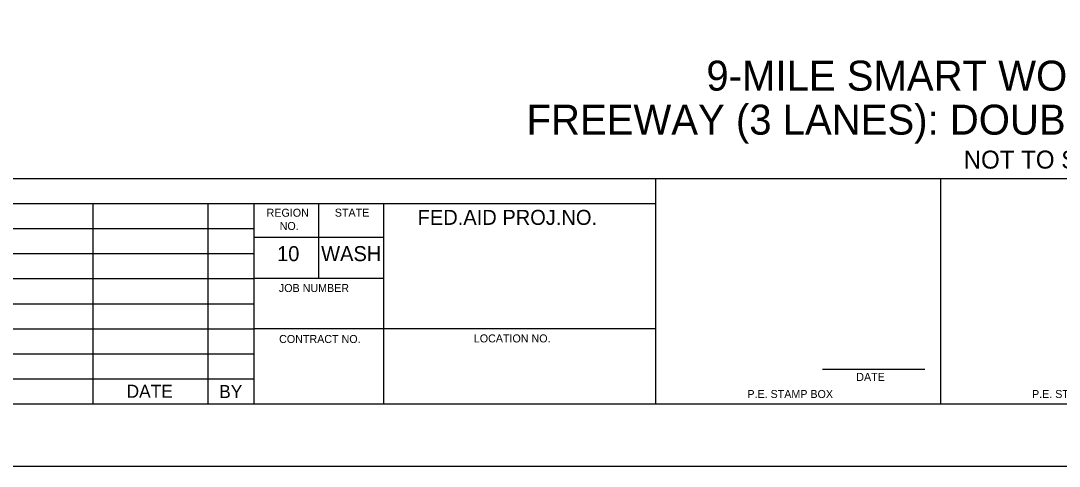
# Model space of a CAD drawing. Extents: x 99999.1 to 100055.7, y 99995 to 100017.5.
# Drawn here: x 100024.28 to 100029.47, y 99999.69 to 100001.92 of the extents above; entities that cross this region are included whole.
import ezdxf

# ---------------------------------------------------------------- set-up
doc = ezdxf.new("R2010")
doc.units = 0
for name, color, linetype in [('SH_DE_DetailHeading1Text', 7, 'Continuous'), ('SH_DE_DetailHeading3Text', 7, 'Continuous'), ('SH_GI_PlotLimits', 7, 'Continuous'), ('SH_GI_SheetBorder', 7, 'Continuous'), ('SH_GI_SheetTextInCells', 7, 'Continuous')]:
    doc.layers.add(name, color=color, linetype=linetype)

msp = doc.modelspace()

# ---------------------------------------------------------------- linework, layer by layer
at = {"layer": 'SH_GI_PlotLimits'}
msp.add_lwpolyline([(100019.0625, 99999.6875), (100036.0625, 99999.6875), (100036.0625, 100010.6875), (100019.0625, 100010.6875)], close=True, dxfattribs=at)
at = {"layer": 'SH_GI_SheetBorder'}
for p, q in [((100020, 100001.1259), (100035.75, 100001.1259)), ((100027.4566, 100000), (100027.4566, 100001.1259)), ((100028.8828, 100000), (100028.8828, 100001.1259)), ((100020, 100001.0008), (100027.4566, 100001.0008)), ((100024.641, 100001.0008), (100024.641, 100000)), ((100025.2164, 100001.0008), (100025.2164, 100000)), ((100025.4451, 100001.0008), (100025.4451, 100000)), ((100025.7719, 100000.6255), (100025.7719, 100001.0008)), ((100026.0956, 100000), (100026.0956, 100001.0008)), ((100022.1821, 100000.8757), (100025.4466, 100000.8757)), ((100026.0958, 100000.831), (100025.4466, 100000.831)), ((100022.1821, 100000.7506), (100025.4466, 100000.7506)), ((100020, 100000.6255), (100025.4466, 100000.6255)), ((100026.0958, 100000.6255), (100025.4466, 100000.6255)), ((100020, 100000.5004), (100025.4466, 100000.5004)), ((100020, 100000.3753), (100025.4466, 100000.3753)), ((100027.4566, 100000.3753), (100025.4466, 100000.3753)), ((100020, 100000.2502), (100025.4466, 100000.2502)), ((100028.2903, 100000.1733), (100028.802, 100000.1733)), ((100020, 100000.1251), (100025.4466, 100000.1251)), ((100020, 100000), (100035.75, 100000))]:
    msp.add_line(p, q, dxfattribs=at)

# ---------------------------------------------------------------- texts
at = {"layer": 'SH_DE_DetailHeading1Text'}
for s, p in [('9-MILE SMART WORK ZONE SYSTEM', (100027.7097, 100001.5658)), ('FREEWAY (3 LANES): DOUBLE RIGHT LANE CLOSURE', (100026.81, 100001.3458))]:
    msp.add_text(s, height=0.15, dxfattribs=at).set_placement(p)
at = {"layer": 'SH_DE_DetailHeading3Text'}
msp.add_text('NOT TO SCALE', height=0.09, dxfattribs=at).set_placement((100028.9969, 100001.1759))
at = {"layer": 'SH_GI_SheetTextInCells'}
for s, height, p in [('REGION', 0.04003, (100025.5099, 100000.9352)), ('STATE', 0.04003, (100025.8511, 100000.9357)), ('FED.AID PROJ.NO.', 0.07506, (100026.2652, 100000.8945)), ('NO.', 0.04003, (100025.5752, 100000.869)), ('10', 0.07506, (100025.5621, 100000.7131)), ('WASH', 0.07506, (100025.7826, 100000.7131)), ('JOB NUMBER', 0.04003, (100025.5712, 100000.5587)), ('CONTRACT NO.', 0.040032, (100025.5725, 100000.3037)), ('LOCATION NO.', 0.040032, (100026.5465, 100000.3067)), ('DATE', 0.04003, (100028.4597, 100000.1141)), ('DATE', 0.06505, (100024.8091, 100000.03)), ('BY', 0.06505, (100025.2725, 100000.0285)), ('P.E. STAMP BOX', 0.040032, (100027.915, 100000.0286)), ('P.E. STAMP BOX', 0.040032, (100029.339, 100000.0286))]:
    msp.add_text(s, height=height, dxfattribs=at).set_placement(p)

doc.saveas('drawing.dxf')
